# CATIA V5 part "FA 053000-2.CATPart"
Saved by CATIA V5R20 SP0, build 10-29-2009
Part number: FA 053000-2
Revision: ANY
Definition: UNKNOWN
Nomenclature: FA 053000-2
Source: Unknown
Bounding box of the stored display mesh (mm): x -1.5 to 1.5, y 0 to 3.7, z -1.5 to 1.5
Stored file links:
  C:\Users\Utente\Desktop\IO LAVORO\3D X SITO CF\CUMSA\3D files FA\FA 0530SF\FA 053000-2.CATPart

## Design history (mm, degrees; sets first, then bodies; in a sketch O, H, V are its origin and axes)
Body1 "Cortar-Extruir1" (main body)
  Solid1: solid without history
